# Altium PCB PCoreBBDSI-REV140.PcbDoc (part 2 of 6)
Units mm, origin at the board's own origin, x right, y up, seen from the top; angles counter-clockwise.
Board outline 100 x 72 mm, 6 copper layers (Top Layer, Int1 (GND), Int2 (Sign), Int3 (Sign), Int4 (GND), Bottom Layer), stack 1.551 mm thick; 358 components, 403 nets, 1535 pads, 844 vias.
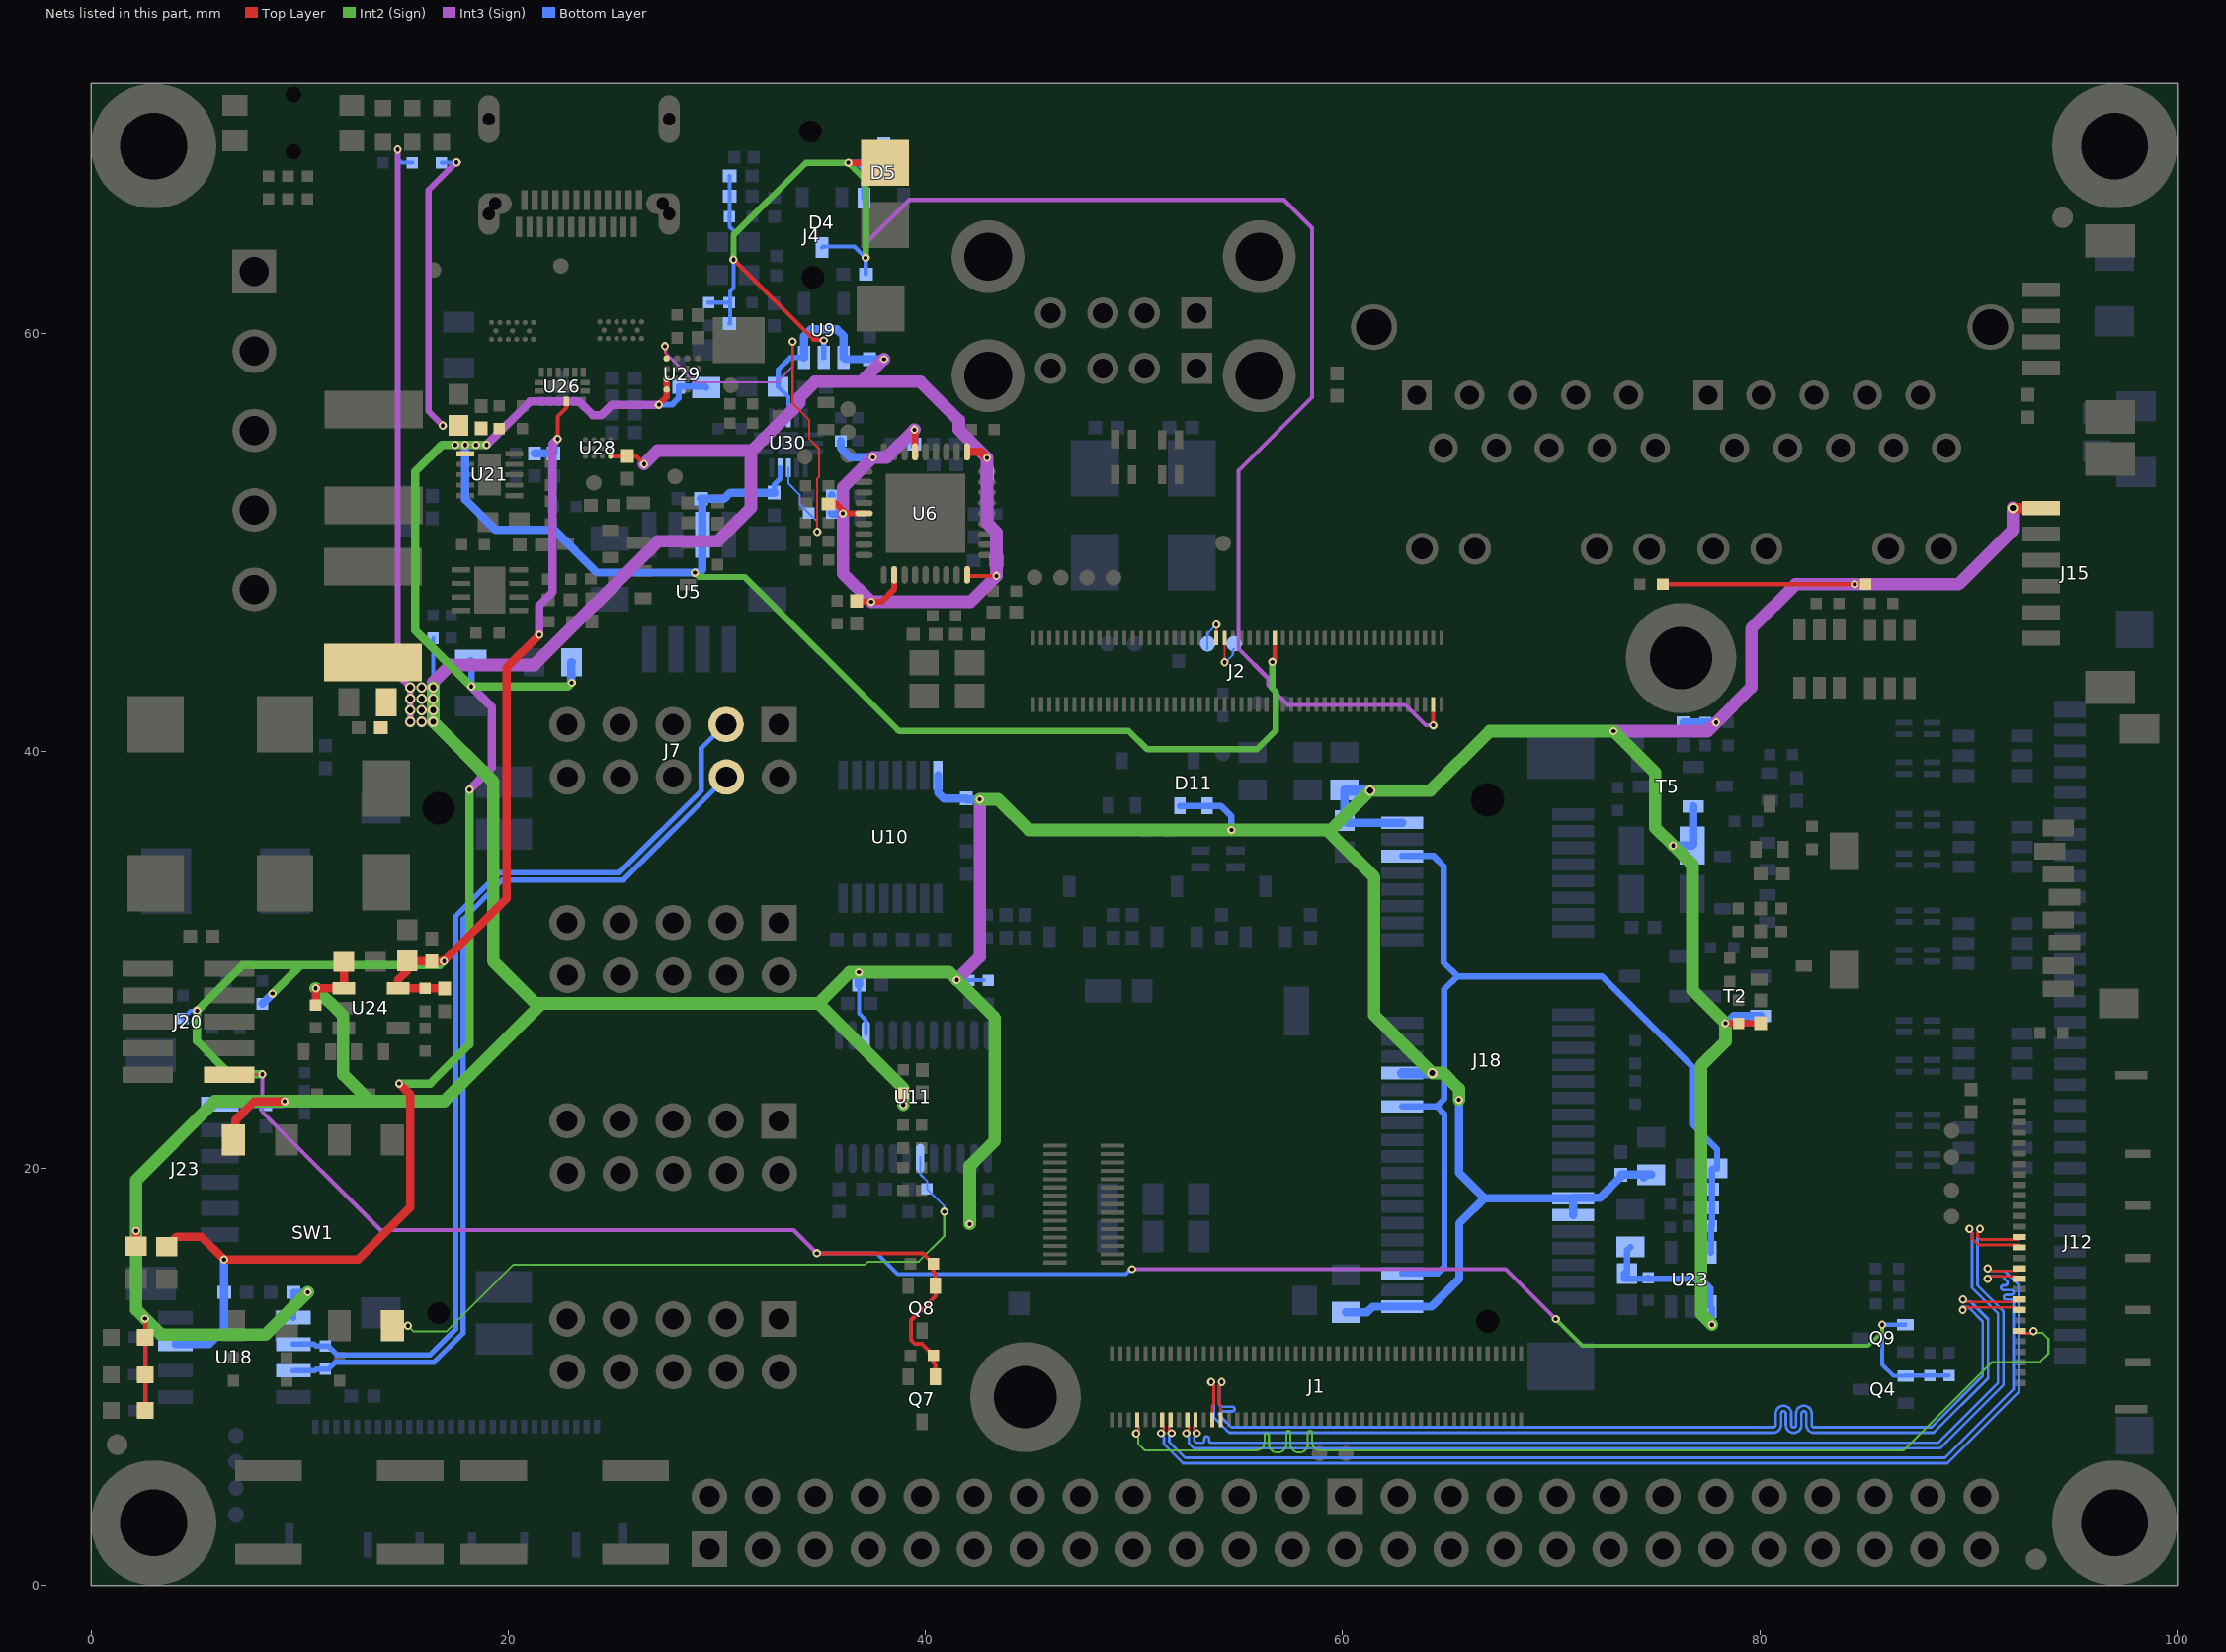
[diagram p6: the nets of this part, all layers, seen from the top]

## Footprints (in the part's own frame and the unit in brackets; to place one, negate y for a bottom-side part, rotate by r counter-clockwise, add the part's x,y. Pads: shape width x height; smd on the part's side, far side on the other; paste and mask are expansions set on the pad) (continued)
"F&S LOGO 5x5mm" [mm]
  Top Layer region: 0.175,2.098 0.382,2.013 0.578,1.917 0.765,1.813 0.941,1.699 1.105,1.577 1.257,1.448 1.396,1.31 1.522,1.166 1.633,1.015 1.73,0.858 1.811,0.696 1.875,0.528 1.923,0.356 1.953,0.18 1.966,0 0.226,0 0.138,0.011 0.072,0.041 0.026,0.083 -0.006,0.132 -0.025,0.18 -0.035,0.223 -0.04,0.265 -0.04,2.173
  Top Layer pour cut-out: 0.678,2.643 0.717,2.631 0.759,2.627 0.801,2.631 0.84,2.642 0.874,2.661 0.904,2.687 0.928,2.722 0.946,2.764 0.956,2.814 0.96,2.872 0.96,3.525 1.622,3.525 1.702,3.535 1.759,3.566 1.794,3.613 1.805,3.675 1.794,3.737 1.76,3.785 1.703,3.816 1.622,3.827 0.96,3.827 0.96,4.334 1.752,4.334 1.836,4.344 1.869,4.358 1.895,4.376 1.93,4.426 1.942,4.489 1.93,4.552 1.895,4.601 1.869,4.619 1.836,4.633 1.752,4.643 0.804,4.643 0.726,4.637 0.664,4.618 0.616,4.586 0.583,4.539 0.564,4.476 0.558,4.397 0.558,2.872 0.561,2.814 0.572,2.765 0.589,2.723 0.614,2.688 0.644,2.662
  Top Layer pour cut-out: 3.064,0.656 3.027,0.722 3,0.787 2.985,0.851 2.979,0.915 2.992,0.982 3.03,1.04 3.088,1.079 3.159,1.092 3.218,1.082 3.267,1.051 3.308,1.001 3.342,0.931 3.382,0.844 3.424,0.773 3.477,0.715 3.548,0.668 3.641,0.637 3.758,0.627 3.843,0.632 3.92,0.647 3.989,0.673 4.049,0.71 4.098,0.754 4.133,0.803 4.154,0.858 4.161,0.917 4.157,0.964 4.146,1.007 4.127,1.044 4.1,1.078 4.031,1.132 3.945,1.171 3.689,1.24 3.493,1.295 3.331,1.357 3.262,1.394 3.201,1.436 3.148,1.485 3.102,1.54 3.065,1.601 3.038,1.67 3.022,1.745 3.017,1.827 3.023,1.907 3.04,1.982 3.067,2.052 3.107,2.118 3.156,2.178 3.216,2.23 3.286,2.276 3.365,2.313 3.454,2.343 3.55,2.365 3.653,2.377 3.764,2.382 3.934,2.37 4.08,2.336 4.202,2.284 4.301,2.216 4.378,2.139 4.43,2.058 4.461,1.977 4.471,1.898 4.458,1.829 4.42,1.768 4.393,1.743 4.363,1.725 4.33,1.715 4.293,1.711 4.233,1.72 4.188,1.745 4.151,1.791 4.11,1.858 4.051,1.958 3.98,2.033 3.937,2.061 3.881,2.081 3.815,2.092 3.737,2.096 3.662,2.092 3.596,2.079 3.537,2.058 3.485,2.028 3.443,1.992 3.414,1.953 3.396,1.91 3.39,1.864 3.398,1.808 3.422,1.761 3.461,1.721 3.512,1.687 3.627,1.638 3.819,1.587 3.979,1.545 4.123,1.5 4.249,1.448 4.355,1.385 4.44,1.309 4.504,1.214 4.527,1.159 4.544,1.099 4.558,0.961 4.552,0.873 4.534,0.79 4.505,0.711 4.465,0.637 4.413,0.57 4.35,0.51 4.277,0.457 4.193,0.413 4.1,0.377 3.998,0.352 3.888,0.337 3.769,0.332 3.628,0.339 3.501,0.359 3.386,0.394 3.284,0.443 3.219,0.486 3.161,0.536 3.109,0.592
  Top Layer region: 2.907,3.777 2.992,3.656 3.084,3.538 3.185,3.423 3.293,3.312 3.408,3.204 3.532,3.1 3.662,2.999 3.807,2.899 3.957,2.806 4.112,2.718 4.273,2.637 4.438,2.563 4.608,2.495 4.782,2.433 4.96,2.378 4.96,0.265 4.949,0.178 4.919,0.112 4.877,0.065 4.828,0.034 4.78,0.015 4.737,0.005 4.694,0 2.401,0 2.831,3.901 hole: 3.764,2.382 3.653,2.377 3.55,2.365 3.454,2.343 3.365,2.313 3.286,2.276 3.216,2.23 3.156,2.178 3.107,2.118 3.067,2.052 3.04,1.982 3.023,1.907 3.017,1.827 3.022,1.745 3.038,1.67 3.065,1.601 3.102,1.54 3.148,1.485 3.201,1.436 3.262,1.394 3.331,1.357 3.493,1.295 3.689,1.24 3.945,1.171 4.031,1.132 4.1,1.078 4.127,1.044 4.146,1.007 4.157,0.964 4.161,0.917 4.154,0.858 4.133,0.803 4.098,0.754 4.049,0.71 3.989,0.673 3.92,0.647 3.843,0.632 3.758,0.627 3.641,0.637 3.548,0.668 3.477,0.715 3.424,0.773 3.382,0.844 3.342,0.931 3.308,1.001 3.267,1.051 3.218,1.082 3.159,1.092 3.088,1.079 3.03,1.04 2.992,0.982 2.979,0.915 2.985,0.851 3,0.787 3.027,0.722 3.064,0.656 3.109,0.592 3.161,0.536 3.219,0.486 3.284,0.443 3.386,0.394 3.501,0.359 3.628,0.339 3.769,0.332 3.888,0.337 3.998,0.352 4.1,0.377 4.193,0.413 4.277,0.457 4.35,0.51 4.413,0.57 4.465,0.637 4.505,0.711 4.534,0.79 4.552,0.873 4.558,0.961 4.544,1.099 4.527,1.159 4.504,1.214 4.44,1.309 4.355,1.385 4.249,1.448 4.123,1.5 3.979,1.545 3.819,1.587 3.627,1.638 3.512,1.687 3.461,1.721 3.422,1.761 3.398,1.808 3.39,1.864 3.396,1.91 3.414,1.953 3.443,1.992 3.485,2.028 3.537,2.058 3.596,2.079 3.662,2.092 3.737,2.096 3.815,2.092 3.881,2.081 3.937,2.061 3.98,2.033 4.051,1.958 4.11,1.858 4.151,1.791 4.188,1.745 4.233,1.72 4.293,1.711 4.33,1.715 4.363,1.725 4.393,1.743 4.42,1.768 4.458,1.829 4.471,1.898 4.461,1.977 4.43,2.058 4.378,2.139 4.301,2.216 4.202,2.284 4.08,2.336 3.934,2.37
  Top Layer region: 4.782,4.989 4.848,4.959 4.894,4.917 4.926,4.868 4.945,4.82 4.955,4.778 4.96,4.735 4.96,2.827 4.745,2.902 4.538,2.987 4.342,3.083 4.155,3.187 3.979,3.301 3.815,3.423 3.663,3.552 3.524,3.69 3.398,3.834 3.287,3.985 3.19,4.142 3.109,4.304 3.045,4.472 2.997,4.644 2.966,4.82 2.954,5 4.694,5
  Top Layer region: 2.089,1.099 2.012,1.223 1.928,1.344 1.836,1.462 1.735,1.577 1.627,1.688 1.512,1.796 1.388,1.9 1.257,2.001 1.113,2.101 0.963,2.194 0.808,2.282 0.647,2.363 0.482,2.437 0.312,2.505 0.138,2.567 -0.04,2.621 -0.04,4.735 -0.029,4.822 0.001,4.888 0.043,4.935 0.092,4.966 0.14,4.985 0.183,4.995 0.226,5 2.519,5 hole: 1.752,4.643 0.804,4.643 0.726,4.637 0.664,4.618 0.616,4.586 0.583,4.539 0.564,4.476 0.558,4.397 0.558,2.872 0.561,2.814 0.572,2.765 0.589,2.723 0.614,2.688 0.644,2.662 0.678,2.643 0.717,2.631 0.759,2.627 0.801,2.631 0.84,2.642 0.874,2.661 0.904,2.687 0.928,2.722 0.946,2.764 0.956,2.814 0.96,2.872 0.96,3.525 1.622,3.525 1.702,3.535 1.759,3.566 1.794,3.613 1.805,3.675 1.794,3.737 1.76,3.785 1.703,3.816 1.622,3.827 0.96,3.827 0.96,4.334 1.752,4.334 1.836,4.344 1.869,4.358 1.895,4.376 1.93,4.426 1.942,4.489 1.93,4.552 1.895,4.601 1.869,4.619 1.836,4.633
FH41-28S-0.5SH(05) [mm]
  rect 0.3x0.65 smd mask+0: 1(-6.75,2.975) 2(-6.25,2.975) 3(-5.75,2.975) 4(-5.25,2.975) 5(-4.75,2.975) 6(-4.25,2.975) 7(-3.75,2.975) 8(-3.25,2.975) 9(-2.75,2.975) 10(-2.25,2.975) 11(-1.75,2.975) 12(-1.25,2.975) 13(-0.75,2.975) 14(-0.25,2.975) 15(0.25,2.975) 16(0.75,2.975) 17(1.25,2.975) 18(1.75,2.975) 19(2.25,2.975) 20(2.75,2.975) 21(3.25,2.975) 22(3.75,2.975) 23(4.25,2.975) 24(4.75,2.975) 25(5.25,2.975) 26(5.75,2.975) 27(6.25,2.975) 28(6.75,2.975)
  rect 0.4x1.2 smd mask+0: 29(-5.75,-2.7) 30(-3.25,-2.7) 31(-0.75,-2.7) 32(1.75,-2.7) 33(4.25,-2.7)
  rect 0.4x1.55 smd mask+0: 40(-8,-2.4) 41(8,-2.4)
  body extent -9,-3.12 9,3.13, height 2.5
FIDUCIAL [mm] "Fiducial IPC2221A"
  round 1 smd paste+0 mask+0.5: 1(0,0)
  Top Layer keep-out circle w0.1: c0,0 r0.9
FUSE0805 [mm]
  rect 1x1.5 smd paste+0: 1(-1.1,0) 2(1.1,0)
  body extent -1.07,-0.67 1.07,0.67, height 1
HOLE-3.2x6 [mm]
  round 6 hole 3.2 paste+0 mask+0: 1(0,0)
HUQFN16 [mm]
  rect 0.25x0.45 smd paste-0.025 mask+0: 1(-1,-0.7) 2(-0.6,-0.7) 3(-0.2,-0.7) 4(0.2,-0.7) 5(0.6,-0.7) 6(1,-0.7) 9(1,0.7) 10(0.6,0.7) 11(0.2,0.7) 12(-0.2,0.7) 13(-0.6,0.7) 14(-1,0.7)
  rect 0.45x0.25 smd mask+0: 7(1.1,-0.2) 8(1.1,0.2) 15(-1.1,0.2) 16(-1.1,-0.2)
  rect 1.4x0.6 smd paste-10 mask+0: 17(0,0)
  body extent -1.23,-0.82 1.22,0.83, height 0.55
HX2QFN16 [mm] "QFN, 16-Leads, Body 2,60x2,60mm, Pitch 0,40mm, Thermal Pad 1,10x1,00mm, IPC Medium Density"
  rect 0.24x0.9 smd: 1(-0.8,-1.2) 2(-0.4,-1.2) 3(0,-1.2) 4(0.4,-1.2) 5(0.8,-1.2) 9(0.8,1.2) 10(0.4,1.2) 11(0,1.2) 12(-0.4,1.2) 13(-0.8,1.2)
  rect 0.9x0.24 smd: 6(1.2,-0.4) 7(1.2,0) 8(1.2,0.4) 14(-1.2,0.4) 15(-1.2,0) 16(-1.2,-0.4)
  rect 1x1.1 smd paste-0.25: 17(0,0)
  silkscreen extent -1.5,-2.27 1.5,1.5, body extent -1.35,-1.35 1.35,1.35, height 0.4
J-B2B-5X2-127MM-WR-PHD [mm]
  rect 0.76x2.4 smd paste+0: 1(-2.54,-1.95) 2(-2.54,1.95) 3(-1.27,-1.95) 4(-1.27,1.95) 5(0,-1.95) 6(0,1.95) 7(1.27,-1.95) 8(1.27,1.95) 9(2.54,-1.95) 10(2.54,1.95)
  body extent -3.17,-2.75 3.18,2.75, height 4.5
JAE-30POL. [mm]
  rect 0.6x1.5 smd paste+0.05: 1(14.5,-2.05) 2(13.5,-2.05) 3(12.5,-2.05) 4(11.5,-2.05) 5(10.5,-2.05) 6(9.5,-2.05) 7(8.5,-2.05) 8(7.5,-2.05) 9(6.5,-2.05) 10(5.5,-2.05) 11(4.5,-2.05) 12(3.5,-2.05) 13(2.5,-2.05) 14(1.5,-2.05) 15(0.5,-2.05) 16(-0.5,-2.05) 17(-1.5,-2.05) 18(-2.5,-2.05) 19(-3.5,-2.05) 20(-4.5,-2.05) 21(-5.5,-2.05) 22(-6.5,-2.05) 23(-7.5,-2.05) 24(-8.5,-2.05) 25(-9.5,-2.05) 26(-10.5,-2.05) 27(-11.5,-2.05) 28(-12.5,-2.05) 29(-13.5,-2.05) 30(-14.5,-2.05)
  rect 0.8x1.5 smd paste+0.05: 31(-15.5,-2.05) 32(15.5,-2.05)
  rect 1.8x1.8 smd paste+0.1: 33(-19.325,1.05) 34(19.325,1.05)
  body extent -20.03,-2.28 20.02,2.47, height 2.39
L0402 [mm] "Chip Inductor, 2-Leads, Body 1,00x0,50mm, IPC Medium Density"
  rect 0.59x0.62 smd: 1(-0.455,0) 2(0.455,0)
  body extent -0.53,-0.28 0.53,0.28, height 0.55
L0603 [mm] "Chip Inductor, 2-Leads, Body 1,60x0,80mm, IPC Medium Density"
  rect 0.93x1.02 smd: 1(-0.785,0) 2(0.785,0)
  body extent -0.9,-0.5 0.9,0.5, height 1
L1206 [mm] "Chip Inductor, 2-Leads, Body 3,20x1,60mm, IPC Medium Density"
  rect 1.19x1.82 smd: 1(-1.455,0) 2(1.455,0)
  silkscreen extent -0.5,-0.81 0.5,0.81, body extent -1.7,-0.9 1.7,0.9, height 1.3
LD-5X5M-VLC5045 [mm] "Precision Wire Wound Inductor, 2-Leads, Body 5,00x5,00mm, IPC Medium Density"
  rect 1.8x4.7 smd paste-0.1: 1(-2.3,0) 2(2.3,0)
  silkscreen extent -2.6,-2.6 2.6,2.6, body extent -2.49,-2.47 2.51,2.53, height 3.98
LED0603 [mm]
  rect 0.8x0.8 smd paste+0: 1(-0.825,0) 2(0.825,0)
  body extent -0.81,-0.4 0.8,0.4, height 0.75
LUMBERG-2410-03 [mm]
  round 3.5 hole 2.3 unplated paste+0 mask+0: 9(6.5,-2.85) 10(6.5,2.85) 11(-6.5,2.85) 12(-6.5,-2.85)
  rect 1.5x1.5 hole 0.95 unplated paste+0 mask+0: A1(3.5,0.15) B1(3.5,-2.5)
  round 1.5 hole 0.95 unplated paste+0 mask+0: A2(1,0.15) A3(-1,0.15) A4(-3.5,0.15) B2(1,-2.5) B3(-1,-2.5) B4(-3.5,-2.5)
  body extent -7.5,-4.1 7.5,13.92, height 16.21
MCDM(R)-04-T [mm]
  rect 1.1x1.5 smd: 1(-3.81,-4.45) 2(-1.27,-4.45) 3(1.27,-4.45) 4(3.81,-4.45) 5(3.81,4.45) 6(1.27,4.45) 7(-1.27,4.45) 8(-3.81,4.45)
  body extent -5.55,-4.9 5.55,4.9, height 4.36
MIC2026 [mm]
  rect 2.2x0.7 smd paste+0 mask+0: 1(-2.75,1.905) 2(-2.75,0.635) 3(-2.75,-0.635) 4(-2.75,-1.905) 5(2.75,-1.905) 6(2.75,-0.635) 7(2.75,0.635) 8(2.75,1.905)
  silkscreen extent -4.54,-2.49 1.25,2.49, body extent -3.01,-2.45 3.01,2.45, height 1.63
MICROSD_PUSH-PULL [mm]
  rect 0.8x1.5 smd paste+0.05: 1(-1.85,3.05) 2(-0.75,2.65) 3(0.35,3.05) 4(1.45,3.35) 5(2.55,3.05) 6(3.65,3.35) 7(4.75,3.05) 8(5.85,3.05)
  rect 1.4x1.9 smd paste+0.05: 9(-6.6,6.95) 12(6.55,5.95)
  rect 1.8x1.4 smd paste+0.05: 10(4.95,-7.2) 11(-0.75,-7.2)
  body extent -6.94,-7.6 7.06,7.6, height 1.83
MM60-52B1-E1-R650 [mm]
  rect 0.6x2 smd mask+0: 1(-11.8,-4.1) 2(-11.4,4.1) 3(-11,-4.1) 4(-10.6,4.1) 5(-10.2,-4.1) 6(-9.8,4.1) 7(-9.4,-4.1) 8(-9,4.1) 9(-8.6,-4.1) 10(-8.2,4.1) 11(-7.8,-4.1) 12(-7.4,4.1) 13(-7,-4.1) 14(-6.6,4.1) 15(-6.2,-4.1) 16(-5.8,4.1) 17(-2.2,-4.1) 18(-1.8,4.1) 19(-1.4,-4.1) 20(-1,4.1) 21(-0.6,-4.1) 22(-0.2,4.1) 23(0.2,-4.1) 24(0.6,4.1) 25(1,-4.1) 26(1.4,4.1) 27(1.8,-4.1) 28(2.2,4.1) 29(2.6,-4.1) 30(3,4.1) 31(3.4,-4.1) 32(3.8,4.1) 33(4.2,-4.1) 34(4.6,4.1) 35(5,-4.1) 36(5.4,4.1) 37(5.8,-4.1) 38(6.2,4.1) 39(6.6,-4.1) 40(7,4.1) 41(7.4,-4.1) 42(7.8,4.1) 43(8.2,-4.1) 44(8.6,4.1) 45(9,-4.1) 46(9.4,4.1) 47(9.8,-4.1) 48(10.2,4.1) 49(10.6,-4.1) 50(11,4.1) 51(11.4,-4.1) 52(11.8,4.1)
  rect 2.3x3.2 smd: 53(-14.65,-3.5) 54(14.65,-3.5)
  round 0 hole 1.6 unplated: 55(-12.5,0)
  round 0 hole 1.1 unplated: 56(12.5,0)
  body extent -14.85,-5 14.85,5, height 5.8
MM60-EZH059-B5-R650 [mm] "MINI EXPRESS CARD LATCH SMD"
  rect 1.5x2.7 smd paste+0.1 mask+0: ""(-13.35,-3.15) ""(-10.85,-3.15) ""(10.85,-3.15) ""(13.35,-3.15)
  round 0 hole 1.55 unplated: ""(-12.1,0)
  rect 1.5x1.9 smd paste+0.1 mask+0: ""(-12.1,2.75) ""(12.1,2.75)
  round 0 hole 1.05 unplated: ""(12.1,0)
  body extent -14.5,-3.95 14.5,3.95, height 6.8
R0402 [mm] "Chip Resistor, 2-Leads, Body 3,20x2,50mm, IPC Medium Density"
  rect 0.55x0.55 smd: 1(-0.55,0) 2(0.55,0)
  body extent -0.53,-0.28 0.52,0.28, height 0.4
R0805 [mm] "Chip Resistor, 2-Leads, Body 2,00x1,25mm, IPC Medium Density"
  rect 1x1.35 smd: 1(-0.9,0) 2(0.9,0)
  silkscreen extent -0.1,-0.58 0.1,0.58, body extent -1.05,-0.67 1.05,0.67, height 0.6
SF56K006VBAR2000 [mm] "Micro SIM Socket"
  rect 1x1.5 smd mask+0: C1(2.66,-4.34) C2(0.47,-4.34) C3(-1.72,-4.34) C5(2.66,-2.54) C6(0.47,-2.54) C7(-1.72,-2.54)
  rect 1x1.1 smd mask+0: DSW2(1,7.45) HD4(6.9,-7.55)
  rect 1.2x1.4 smd mask+0: HD1(-6.8,-7.4)
  rect 1.2x2.35 smd mask+0: HD2DSW1(-6.4,6.475)
  rect 1.75x1.1 smd mask+0: HD3(2.87,7.45)
  body extent -7.35,-8.1 7.35,8.1, height 1.27
SJ2-3574A-SMT-TR [mm]
  rect 2.2x2.5 smd: 1(5.4,-3.45)
  rect 2.2x2.3 smd: 2(3.9,3.35) 3(-0.1,3.55) 4(-3.1,3.55)
  round 1.1 hole 1.1 unplated: None(-4.6,0) None(2.4,0.1)
  body extent -8.1,-4.2 6.9,4.2, height 5.3
SOIC-8_M [mm] "SOIC, 8-Leads, Body 5x4mm, Pitch 1.27mm, IPC Low Density"
  rect 1.65x0.65 smd: 1(-2.825,1.905) 2(-2.825,0.635) 3(-2.825,-0.635) 4(-2.825,-1.905) 5(2.825,-1.905) 6(2.825,-0.635) 7(2.825,0.635) 8(2.825,1.905)
  silkscreen extent -2.95,-2.5 1.6,2.9, body extent -3,-2.5 3,2.5, height 1.75
SON50P250X80_HS-11N [mm] "SON, 10-Leads, Body 2,50x2,50mm, Pitch 0,50mm, Thermal Pad 2,00x1,09mm, IPC Medium Density"
  rect 0.85x0.25 smd: 1(-1.17,1) 2(-1.17,0.5) 3(-1.17,0) 4(-1.17,-0.5) 5(-1.17,-1) 6(1.17,-1) 7(1.17,-0.5) 8(1.17,0) 9(1.17,0.5) 10(1.17,1)
  rect 1.09x2 smd paste-0.2: 11(0,0)
  silkscreen extent -1.75,-1.45 1.3,1.5, body extent -1.3,-1.3 1.3,1.3, height 0.8
SOT23-3 [mm] "SOT23, 3-Leads, Body 2,92x2,37mm, Pitch 0,95mm, IPC Medium Density"
  rect 1x0.6 smd: 1(-1.2,0.95) 2(-1.2,-0.95) 3(1.2,0)
  silkscreen extent -1.33,-1.5 0.7,1.92, body extent -1.32,-1.52 1.32,1.52, height 1.12
SOT23-5 [mm] "SOT23, 5-Leads, Body 3,00x2,75mm, Pitch 0,95mm, IPC Medium Density"
  rect 1.1x0.6 smd: 1(-1.3,0.95) 2(-1.3,0) 3(-1.3,-0.95) 4(1.3,-0.95) 5(1.3,0.95)
  silkscreen extent -1.42,-1.5 0.35,1.93, body extent -1.5,-1.5 1.5,1.5, height 1.1
SOT23-6 [mm] "SOT23, 6-Leads, Body 2,95x2,95mm, Pitch 0,95mm, IPC Medium Density"
  rect 1.05x0.6 smd: 1(-1.4,0.95) 2(-1.4,0) 3(-1.4,-0.95) 4(1.4,-0.95) 5(1.4,0) 6(1.4,0.95)
  silkscreen extent -1.52,-1.55 0.5,1.92, body extent -1.55,-1.55 1.55,1.55, height 1.45
"SOT323 (SC70)" [mm]
  rect 0.8x0.55 smd: 1(-1.075,0.65) 2(-1.075,-0.65) 3(1.075,0)
  silkscreen extent -1.2,-1.1 0.67,1.6, body extent -1.15,-1.1 1.15,1.1, height 1.1
Spacer_M2 [mm]
  round 5.3 / inner round 0 / far side round 3.4 hole 3 paste+0: 1(0,0)
  body extent -2.17,-2.17 2.18,2.17, height 1.5
TESTPOINT [mm]
  round 0.75 smd paste-1: 1(0,0)
TRJG27440ADNL [mm] "2x RJ45 1000 Base-T integrated magnetics"
  rect 1.42x1.42 hole 0.9 unplated paste+0: L1(-1.27,4.4) R1(12.7,4.4)
  round 1.42 hole 0.9 unplated paste+0: L2(-2.54,6.94) L3(-3.81,4.4) L4(-5.08,6.94) L5(-6.35,4.4) L6(-7.62,6.94) L7(-8.89,4.4) L8(-10.16,6.94) L9(-11.43,4.4) L10(-12.7,6.94) R2(11.43,6.94) R3(10.16,4.4) R4(8.89,6.94) R5(7.62,4.4) R6(6.35,6.94) R7(5.08,4.4) R8(3.81,6.94) R9(2.54,4.4) R10(1.27,6.94)
  round 1.54 hole 1.02 unplated paste+0: L11(-1.525,11.77) L12(-4.065,11.77) L13(-9.905,11.77) R11(12.445,11.77) R12(9.905,11.77) R13(4.065,11.77) R14(1.55,11.79)
  round 1.542 hole 1.02 unplated paste+0: L14(-12.445,11.77)
  round 2.22 hole 1.7 unplated paste+0: L15(-14.8,1.14) R15(14.75,1.14)
  body extent -16.43,-12.7 16.4,12.7, height 15.28
TSSOP16-065M [mm] "TSOP, 16-Leads, Body 5,00x4,40mm, Pitch 0,65mm, IPC Medium Density"
  rect 1.4x0.45 smd: 1(-2.95,2.275) 2(-2.95,1.625) 3(-2.95,0.975) 4(-2.95,0.325) 5(-2.95,-0.325) 6(-2.95,-0.975) 7(-2.95,-1.625) 8(-2.95,-2.275) 9(2.95,-2.275) 10(2.95,-1.625) 11(2.95,-0.975) 12(2.95,-0.325) 13(2.95,0.325) 14(2.95,0.975) 15(2.95,1.625) 16(2.95,2.275)
  silkscreen extent -3.07,-2.55 1.85,3.18, body extent -3.2,-2.55 3.2,2.55, height 1.2
TSSOP24_065P [mm] "TSOP, 24-Leads, Body 7,80x4,40mm, Pitch 0,65mm, IPC Medium Density"
  oval 1.4x0.4 smd: 1(-2.95,3.575) 2(-2.95,2.925) 3(-2.95,2.275) 4(-2.95,1.625) 5(-2.95,0.975) 6(-2.95,0.325) 7(-2.95,-0.325) 8(-2.95,-0.975) 9(-2.95,-1.625) 10(-2.95,-2.275) 11(-2.95,-2.925) 12(-2.95,-3.575) 13(2.95,-3.575) 14(2.95,-2.925) 15(2.95,-2.275) 16(2.95,-1.625) 17(2.95,-0.975) 18(2.95,-0.325) 19(2.95,0.325) 20(2.95,0.975) 21(2.95,1.625) 22(2.95,2.275) 23(2.95,2.925) 24(2.95,3.575)
  silkscreen extent -3.07,-3.95 1.85,4.45, body extent -3.2,-3.95 3.2,3.95, height 1.2
UC-3019-2GNB-RR [mm]
  rect 0.3x0.95 smd mask+0: A1(-2.63,3.825) A2(-2.13,3.825) A3(-1.63,3.825) A4(-1.13,3.825) A5(-0.63,3.825) A6(-0.13,3.825) A7(0.37,3.825) A8(0.87,3.825) A9(1.37,3.825) A10(1.87,3.825) A11(2.37,3.825) A12(2.87,3.825) B1(2.62,2.525) B2(2.12,2.525) B3(1.62,2.525) B4(1.12,2.525) B5(0.62,2.525) B6(0.12,2.525) B7(-0.38,2.525) B8(-0.88,2.525) B9(-1.38,2.525) B10(-1.88,2.525) B11(-2.38,2.525) B12(-2.88,2.525)
  oval 1x2 hole 0.6 slot 1.6 at 90 deg mask+0: SH1(-4.32,3.2) SH2(4.32,3.2)
  oval 1.6x1 hole 0.6 slot 1.2 at 0 deg mask+0: SH1(-4.02,2.7) SH2(4.02,2.7)
  oval 1x2.3 hole 0.6 slot 1.9 at 90 deg mask+0: SH3(-4.32,-1.35) SH4(4.32,-1.35)
  body extent -4.47,-4.05 4.47,4.05, height 3.26
USB2514 [mm]
  oval 0.85x0.3 smd paste+0 mask+0: 1(-2.95,2) 2(-2.95,1.5) 3(-2.95,1) 4(-2.95,0.5) 5(-2.95,0) 6(-2.95,-0.5) 7(-2.95,-1) 8(-2.95,-1.5) 9(-2.95,-2) 19(2.95,-2) 20(2.95,-1.5) 21(2.95,-1) 22(2.95,-0.5) 23(2.95,0) 24(2.95,0.5) 25(2.95,1) 26(2.95,1.5) 27(2.95,2)
  oval 0.3x0.85 smd paste+0 mask+0: 10(-2,-2.95) 11(-1.5,-2.95) 12(-1,-2.95) 13(-0.5,-2.95) 14(0,-2.95) 15(0.5,-2.95) 16(1,-2.95) 17(1.5,-2.95) 18(2,-2.95) 28(2,2.95) 29(1.5,2.95) 30(1,2.95) 31(0.5,2.95) 32(0,2.95) 33(-0.5,2.95) 34(-1,2.95) 35(-1.5,2.95) 36(-2,2.95)
  rect 3.8x3.8 smd paste-5 mask+0: 37(0,0)
  silkscreen extent -4.08,-3.05 3.05,3.05, body extent -3.03,-3 2.97,3, height 1.03
USBSHOCK4-0805-12 [mm] "Chip Common Mode Choke Coil"
  rect 0.9x0.4 smd paste+0 mask+0: 1(-0.85,0.4) 2(0.85,0.4) 3(0.85,-0.4) 4(-0.85,-0.4)
  body extent -1,-0.6 1,0.6, height 1.2
WDFN8_0.65P_300X80 [mm] "WDFN, 8-Leads, Body 3,00x3,00mm, Pitch 0,65mm, Thermal Pad 2,23x1,48mm, IPC Medium Density"
  rect 0.9x0.25 smd mask+0: 1(-1.39,0.975) 2(-1.39,0.325) 3(-1.39,-0.325) 4(-1.39,-0.975) 5(1.39,-0.975) 6(1.39,-0.325) 7(1.39,0.325) 8(1.39,0.975)
  rect 1.48x2.23 smd paste-10 mask+0: 9(0,0)
  silkscreen extent -2.12,-1.68 1.68,1.72, body extent -1.58,-1.53 1.58,1.53, height 0.8
WE-SL5 [mm] "SMD Inductor, Body 9.0 x 10.3 mm"
  rect 2.7x2.7 smd: 1(-3.81,-3.11) 2(3.81,-3.11) 3(3.81,3.11) 4(-3.81,3.11)
  silkscreen extent -5.08,-4.44 5.08,4.44, body extent -5,-4.35 5,4.35, height 5.6
WLCSP12 [mm] "BGA, 12-Leads, Body 1,27x1,67mmx0,56mm, Pitch 0,40mm"
  round 0.25 smd: A1(-0.6,-0.4) A2(-0.6,0) A3(-0.6,0.4) B1(-0.2,-0.4) B2(-0.2,0) B3(-0.2,0.4) C1(0.2,-0.4) C2(0.2,0) C3(0.2,0.4) D1(0.6,-0.4) D2(0.6,0) D3(0.6,0.4)
  silkscreen extent -0.99,-0.79 -0.89,-0.69, body extent -0.84,-0.63 0.83,0.64, height 0.55
WLCSP15 [mm] "BGA, 15-Leads, Body 2,37x1,17mmx0,60mm, Pitch 0,40mm"
  round 0.25 smd paste+0 mask+0.038: A1(-0.4,-1) A2(-0.4,-0.6) A3(-0.4,-0.2) A4(-0.4,0.2) A5(-0.4,0.6) A6(-0.4,1) B1(0,-0.8) B2(0,0) B3(0,0.8) C1(0.4,-1) C2(0.4,-0.6) C3(0.4,-0.2) C4(0.4,0.2) C5(0.4,0.6) C6(0.4,1)
  silkscreen extent -0.74,-1.34 -0.64,-1.24, body extent -0.59,-1.18 0.58,1.19, height 0.58
WLCSP16 [mm] "BGA, 16-Leads, Body 2,05x2,05mmx0,60mm, Pitch 0,50mm"
  round 0.31 smd: A1(-0.75,-0.75) A2(-0.75,-0.25) A3(-0.75,0.25) A4(-0.75,0.75) B1(-0.25,-0.75) B2(-0.25,-0.25) B3(-0.25,0.25) B4(-0.25,0.75) C1(0.25,-0.75) C2(0.25,-0.25) C3(0.25,0.25) C4(0.25,0.75) D1(0.75,-0.75) D2(0.75,-0.25) D3(0.75,0.25) D4(0.75,0.75)
  silkscreen extent -1.18,-1.18 -1.08,-1.08, body extent -1.02,-1.02 1.02,1.02, height 0.6
XTALD-4-302X205M [mm]
  rect 1.4x1.2 smd paste-0.12: 1(-1.1,-0.8) 2(1.1,-0.8) 3(1.1,0.8) 4(-1.1,0.8)
  body extent -1.61,-1.25 1.61,1.25, height 0.81

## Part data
C1 C2: library part 473, "1nF  10%  2kV  X7R  1206", Temperature=-55/+125°C, Tolerance=10, Voltage=2kV
C3 C6 C7 C8 C9 C10 C11 C12 C13 C14 C19 C21 C22 C25 C33 C34 C35 C36 C37 C38 C39 C40 C41 C42 C43 C44 C45 C46 C47 C49 C50 C53 C54 C60 C66 C69 C70 C71 C74 C76 C78 C80 C82 C86 C90 C93 C94 C95 C96 C97 C100 C101 C105 C106: library part 380, "100nF  10%  16V  X7R  0402", Temperature=-55/+125°C, Tolerance=10, Voltage=16V
C4 C5 C72: library part 718, "220uF  20%  10V  2312  Typ: C", Temperature=-55/+125°C, Tolerance=20, Voltage=10V
C15 C16 C23 C30 C31 C32 C98: library part 394, "10uF  20%  4V  X5R  0402", Temperature=-55/+85°C, Tolerance=20, Voltage=4V
C17 C18 C20: library part 384, "22pF  5%  25V  C0G/NP0  0402", Temperature=-55/+125°C, Tolerance=5, Voltage=25V
C24 C28: library part 374, "220pF  10%  50V  X7R  0402", Temperature=-55/+125°C, Tolerance=10, Voltage=50V
C26 C27 C104: library part 412, "22uF  20%  6,3V  X5R  0603", Temperature=-55/+85°C, Tolerance=0,2, Voltage=6,3V
C29: library part 393, "12pF  5%  50V  C0G/NP0  0402", Temperature=-55/+125°C, Tolerance=5, Voltage=50V
C55 C56 C57 C58 C59: library part 390, "47pF  10%  50V  C0G/NP0  0402", Temperature=-55/+125°C, Tolerance=10, Voltage=50V
C61 C62 C63 C64 C99: library part 442, "47uF  20%  6,3V  X5R  0805", Temperature=-55/+85°C, Tolerance=20, Voltage=6,3V
C65 C75 C77 C79 C87 C88 C91 C92: library part 406, "10uF  20%  6,3V  X5R  0603", Temperature=-55/+85°C, Tolerance=20, Voltage=6,3V
C81: library part 387, "100pF  5%  25V  C0G/NP0  0402", Temperature=-55/+125°C, Tolerance=5, Voltage=25V
C83: library part 439, "0,22uF  10%  6,3V  X7R  0805", Temperature=-55/+125°C, Tolerance=10, Voltage=6,3V
C84 C85 C89: library part 388, "560pF  5%  25V  X7R  0402", Temperature=-55/+125°C, Tolerance=5, Voltage=25V
C102: library part 381, "1nF  10%  25V  X7R  0402", Temperature=-55/+125°C, Tolerance=10, Voltage=25V
C103: library part 392, "2,2uF  20%  6,3V  X5R  0402", Temperature=-55/+85°C, Tolerance=20, Voltage=6,3V
D1 D3 D10 D11 D12: library part 2695, "BAT54CW  30V  200mA  Dual Common Cathode SOT-323", Power=200mA, Temperature=-55°C/+125°C, Voltage=30V
D2 D4 D5 D6 D7 D8: library part 2709, "2 Channel ESD Protection TVS Diode SOT-23-3", Number devices in Package=1, Part Number=PGB102ST23WR, Temperature=-65/+125°C
D9: library part 2696, "SK56L-TP  60V  5A  Common Anode  DO-214AB", Power=5A, Temperature=-55°C/+150°C, Voltage=60V
D13 D14 D15 LED1 LED2 LED3: library part 2744, "LED  Green  View 120°  0603", Part Number=APT1608CGCK
F1 F2: library part 2718, "FUSE PTC RESETTABLE SMD 0805", Temperature=-40/+85°C
J3: library part 2764, "30 pol. 2 reih. Steckerl. SMD RM0,4"
J4: library part 2711, "Audio-Buchse liegend HP+MIC"
J5: library part 2784, "USB Typ C Buchse liegend SMD"
J6: library part 2712, "SD-CARD Micro Steckverbinder push-pull", Part Number="693 071 010 811"
J7 J8 J9 J10: library part 2714, "Stiftl. mit Wanne 10 pol. 2 reih.  steh."
J11: library part 2717, "Stiftl. 50 pol. 2 reih. RM2,54 H=5,8mm"
J12 J22: library part 2781, Temperature=-40/+105°C
J13: library part 2728, "FPC 30 pol. 1.00mm side entry SMT"
J14: library part 2721, "Stiftl. 4 pol. crimpable  liegend RM:1.25"
J15 J23: library part 2720, "Stiftl. 6 pol. crimpable  liegend RM:1.25"
J17: library part 2727, "Micro SIM Steckverbinder push-push"
J18: library part 2713, "mini PCIe SMD 52 pin", Part Number=MM60-52B1-E1-R650
J19: library part 2729, "Stiftl. 5 pol.1 reih. R3,81  liegend"
J20: library part 2706, "Stiftl. 10 pol. 2 reih. SMD RM:1,27", Part Number=M50-3610542
J21: library part 2704, "USB-Einbaukupplung zweifach liegend Typ A", Part Number="2410 03"
L1 L2 L11 L16: library part 2705, "WE-CBF  25%  700R  90MHz  EMI  1206", Part Number=74279218, Temperature=-55/+125°C
L3 L4 L22: library part 2698, "Common Mode Choke  20%  2x 90 Ohm  0805", Power=400mA, Temperature=-40°C/+125°C, Tolerance=20%
L5 L6 L7: library part 2708, "WE-CBF  25%  120R  100MHz  EMI  0402", Part Number=74279271, Temperature=-55/+125°C
L8 L9: library part 2707, "Ferritperlen  25%  120R  100MHz  0603", Part Number=74279262, Temperature=-55/+125°C
L10 L12 L13 L14 L15 L17 L18 L19 L20 L21: library part 2731, "Common Mode Choke  20%  2x 90 Ohm  0504", Part Number=DLP11SN900HL2L, Power=150mA, Temperature=-40/+85°C, Tolerance=20%, Voltage=5V
L23: library part 2697, "2x470uH 1,6A SMD", Power=1,6A
L24 L25: library part 2741, Power=4A
M1: library part 2734, "MINI EXPRESS CARD LATCH SMD"
Q1 Q2 Q5 Q6 T1 T3 T4 T6: library part 2689, "BSS138W SOT323(SC-70) N-Kanal", Temperature=-55°C/150°C
Q3: library part 2757, "24MHz 12pF 3.2x2.5 SMD", Part Number=Q22FA2380038014, Temperature=-40/+85°C
Q4 Q7 Q8 Q9: library part 2772, "MOSFET N-CH 20V 1.4A SOT323(SC-70)", Power=0,5W, Temperature=-55°C/150°C, Voltage=20V
R1: library part 6, "0R00 0,125W max 5% SMD 0805", Power=0,125W, Tolerance=5
R2 R76: library part 187, "0,01R 1/4W max 5% SMD 0805", Power=1/4W, Tolerance=5
R3 R4 R6 R7 R14 R15 R16 R17 R18 R21 R30 R31 R34 R35 R36 R37 R38 R54 R55 R56 R60 R62 R68 R78 R83 R86 R92 R93 R94 R96 R98: library part 170, "10k 1/16W 1% SMD 0402", Power=1/16W, Tolerance=1
R5 R8 R9 R48 R50 R99 R100 R101: library part 184, "4k7 1/16W max 5% SMD 0402", Power=1/16W, Tolerance=5
R10 R11 R32 R33 R39 R40 R41 R42 R69 R70 R95 R97 R102: library part 173, "0R 1/16W max 5% SMD 0402", Power=1/16W, Tolerance=5
R12 R91: library part 180, "1M 1/16W 1% SMD 0402", Power=1/16W, Tolerance=1
R13: library part 183, "12k 1/16W 1% SMD 0402", Power=1/16W, Tolerance=1
R19 R49 R65 R66 R73: library part 177, "100k 1/16W 1% SMD 0402", Power=1/16W, Tolerance=1
R20 R23 R24 R28 R29: library part 170, "10k 1/16W 1% SMD 0402", Part Number=10k, Power=1/16W, Tolerance=1
R22 R43 R44 R45 R57 R58 R59 R79: library part 166, "1k 1/16W 1% SMD 0402", Power=1/16W, Tolerance=1
R25 R27: library part 242, "49R9 1/16W 1% SMD 0402", Power=1/16W, Tolerance=1
R26 R47 R71: library part 186, "47k 1/16W 1% SMD 0402", Power=1/16W, Tolerance=1
R46: library part 179, "22k 1/16W 1% SMD 0402", Power=1/16W, Tolerance=1
R51: library part 309, "120R 1/16W 1% SMD 0402", Power=1/16W, Tolerance=1
R52 R53: library part 190, "300R 1/16W 1% SMD 0402", Power=1/16W, Tolerance=1
R63: library part B.R000.2.S, "0R00 0,125W max 5% SMD 0805", Part Number=0R00, Power=0,125W, Tolerance=5
R64 R84 R87: library part 204, "150k 1/16W 1% SMD 0402", Power=1/16W, Tolerance=1
R67: library part 303, "16.5k 1/16W 1% SMD 0402", Power=1/16W, Tolerance=1
R72 R85: library part 191, "75k 1/16W 1% SMD 0402", Power=1/16W, Tolerance=1
R74: library part Resistor
R75: library part 197, "30k1 1/16W 1% SMD 0402", Power=1/16W, Tolerance=1
R77: library part 254, "24k 1/16W 1% SMD 0402", Power=1/16W, Tolerance=1
R80 R82: library part 172, "150R 1/16W 1% SMD 0402", Power=1/16W, Tolerance=1
R81: library part 174, "221R 1/16W 1% SMD 0402", Power=1/16W, Tolerance=1
R88: library part 326, "56k 1/16W 1% SMD 0402", Power=1/16W, Tolerance=1
R89: library part 337, "23K2 / 1/16W / 1% / SMD / 0402", Power=1/16W, Tolerance=1
R90: library part 273, "53k6 1/16W 1% SMD 0402", Power=1/16W, Tolerance=1
SP1 SP2: library part 2747, "SMD-Distanzbolzen 1.5mm M2", Part Number=9774015243R
SW1: "Kodierschalter 4 pol. SMD", Part Number=MCDM(R)-04-T
T2 T5: library part 2691, "Si2301BDS SOT-23 P-Kanal", Temperature=-55°C/150°C
T10 T11: library part 2735, "Miniatur-Tastschalter Serie EVQ SMD", Power="20 mA", Temperature=-40/+85°C, Voltage=15V
T12: library part 2736, "Tact Switch side push", Temperature=-40/+85°C, Voltage=12V
U5: library part 1285, "MIC2026-1 USB Power Switch", Temperature=-40°C/+85°C, Voltage=2.7...5.5V
U6: library part 1255, "USB2514B C-Temp.", Temperature=0°C/+70°C
U7 U8 U12 U13 U14 U15 U16: library part 2710, "4 Channel  5,5V  TVS Diode Array  SOT-23-6", Part Number=AOZ8904CIL, Temperature=-40/+125°C
U9: library part 1748, "LDO 3.3V 600mA SOT-25 SMD", Part Number=AP7365, Power=600mA, Temperature=-40°C/+85°C, Voltage=3.3V
U10: library part 1210, "SP3232ECY SMD TSSOP16  C-Temp.", Temperature=0°C/+70°C, Voltage=3...5,5V
U11: library part 2755, "SP330E / TSSOP24 / SMD / RS-232/RS-485 Transceiver", Part Number=SP330EEY-L/TR, Temperature=-40/+85°C, Voltage=3...5.5V
U18: library part 1269, Temperature=-40°C/+150°C, Voltage=3…5V
U20: library part 1726, "NCP303LSN30T1G  3V  TSOP-5", Temperature=-40/+125°C
U21: library part 2789, "RT6150B DFN10 2.5x2.5mm"
U22: library part 1736, "RT8070ZQW ADJ 4A Sync WDFN-8 (-40°C bis 85°C)", Power=4A, Temperature=-40/+85°C, Voltage="max. 5,5V"
U23 U24: library part 1740, "ADP171AUJZ-R7 ADJ 300mA VIN max. 3,6V TSOT-5 SMD", Power=300mA, Temperature=-40°C/+125°C, Voltage=3,6V
U25 U27: library part 2765, "USB3.0 EMI filter & ESD Protection", Temperature=-40/+125°C, Voltage=-0.5...5V
U26: library part 2766, "High-speed differential 1-to-2 switch", Part Number=CBTU02043HEJ, Temperature=-10/+85°C, Voltage=1.62...3.63V
U28: library part 2767, "USB Type-C CC and SBU Protection IC", Part Number=NX20P0407UK, Temperature=-40/+85°C, Voltage=-0.5...6V
U29: library part 1328, "USB PD and Type-C current-limited power switch"
U30: library part 2770, "USB PD TCPC PHY IC", Temperature=-40/+85°C, Voltage=2.7...5.5V

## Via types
v1: diameter 0.4, hole 0.2, Top Layer to Bottom Layer, tented both sides, 716 vias
v2: diameter 0.5, hole 0.3, Top Layer to Bottom Layer, tented both sides, 102 vias
v3: diameter 0.4, hole 0.2, Top Layer to Bottom Layer, tented bottom, 16 vias
v4: diameter 0.9, hole 0.9, Top Layer to Bottom Layer, 6 vias
v5: diameter 0.5, hole 0.5, Top Layer to Bottom Layer, 2 vias
v6: diameter 3.2, hole 3.2, Top Layer to Bottom Layer, tented both sides, 2 vias

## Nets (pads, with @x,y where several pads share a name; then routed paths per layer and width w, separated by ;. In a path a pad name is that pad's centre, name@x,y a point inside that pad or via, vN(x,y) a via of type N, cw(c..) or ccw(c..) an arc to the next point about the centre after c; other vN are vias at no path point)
+1V5: C85.2 C86.2 C87.2 J18.6 J18.28 J18.48 R84.2 U23.5 | length 48.5
  Bottom Layer w0.305: J18.48@62.85,14.96 64.56,14.96 64.88,15.28 64.88,22.59 64.51,22.96 ; J18.28@62.85,22.96 64.51,22.96 ; J18.6@62.85,34.96 64.36,34.96 64.85,34.47 64.85,29.85 65.5,29.2 ; U23.5@77.65,15.95 77.65,17.2 77.705,17.255 77.705,18.049 77.71,18.054 C86.2@77.71,19 77.71,19.96 C87.2@77.74,19.99 ; C87.2@77.95,19.99 77.95,20.91 76.75,22.11 76.75,24.87 72.42,29.2 65.5,29.2 ; 64.51,22.96 64.87,23.32 64.87,28.57 65.5,29.2
+1V8: C89.2 C90.2 C91.2 C97.2 C98.2 J20.1 Q4.1 Q7.1 Q8.1 Q9.1 R6.2 R7.2 R50.2 R87.2 R99.2 R100.2 R101.2 U24.5 U26.4 | length 164.3
  Top Layer w0.1: J20.1@6.62,24.48 6.64,24.5 v1(8.21,24.5)
  Top Layer w0.2: v1(22.37,54.96) 22.37,56.04 22.79,56.46 U26.4@22.79,56.76 ; v1(34.79,15.92) 39.88,15.92 R100.2@40.38,15.42 40.38,15.02 40.48,14.92 Q8.1@40.48,14.365 40.48,13.88 39.31,12.71 39.31,11.777 39.497,11.59 39.82,11.59 R99.2@40.38,11.03 40.38,10.69 40.48,10.59 Q7.1@40.48,9.995
  Top Layer w0.4: C89.2@16.95,28.61 16.94,28.62 R87.2@16.02,28.62 U24.5@14.72,28.62 14.72,29.03 15.16,29.47 C91.2@15.16,29.93 16.32,29.93 C90.2@16.33,29.92 16.91,29.92 v1(16.92,29.93) 19.92,32.93 19.92,44 v1(21.493,45.573)
  Int2 (Sign) w0.2: v1(70.21,12.77) 71.49,11.49 85.19,11.49 85.86,12.16 v1(85.86,12.5)
  Int2 (Sign) w0.4: v1(8.21,24.5) 6.68,24.5 5.08,26.1 v1(5.08,27.55) 7.26,29.73 10.06,29.73 ; v1(8.7,28.37) 10.06,29.73 ; 11,29.73 10.06,29.73 ; v1(16.92,29.93) 16.72,29.73 10.06,29.73
  Int3 (Sign) w0.2: v1(8.21,24.5) 8.21,22.7 13.88,17.03 33.68,17.03 v1(34.79,15.92) ; v1(49.896,15.16) 67.82,15.16 v1(70.21,12.77)
  Int3 (Sign) w0.4: v1(21.493,45.573) 21.493,46.983 22.12,47.61 22.12,54.71 v1(22.37,54.96)
  Bottom Layer w0.2: R7.2@4.4,27.18 4.77,27.55 v1(5.08,27.55) ; v1(34.79,15.92) 37.672,15.92 38.672,14.92 49.602,14.92 49.842,15.16 v1(49.896,15.16) ; Q9.1@86.975,12.5 v1(85.86,12.5) 85.86,10.58 86.4,10.04 Q4.1@86.985,10.04 87.005,10.06 R101.2@88.14,10.06 R50.2@89.06,10.06
  Bottom Layer w0.4: R6.2@8.21,27.88 v1(8.7,28.37) ; C98.2@21.26,54.26 C97.2@22.17,54.26 22.17,54.76 v1(22.37,54.96)
+3V3: C9.2 C10.2 C11.2 C12.2 C13.2 C21.2 C31.2 C34.1 C39.1 C44.2 C47.2 C49.2 C61.2 C62.2 C63.2 C64.2 C65.2 C66.2 C82.2 C83.2 C88.2 C92.2 C101.2 C104.2 D11.1 D11.2 J15.1 J18.2 J18.24 J18.39 J18.41 J18.52 J23.1 L8.1 L11.1 L25.2 LED1.2 LED2.2 LED3.2 R11.1 R26.2 R33.1 R34.1 R35.1 R37.1 R46.2 R52.1 R53.1 R72.2 R80.2 R83.1 R86.1 R92.2 R93.2 R98.2 SW1.8 T2.2 T5.2 U6.10 U6.15 U6.23 U6.29 U6.36 U9.1 U9.3 U10.16 U11.3 U18.5 U23.1 U24.1 U28.A3 U30.3 | length 431.4
  Top Layer w0.2: v1(2.59,12.79) 2.605,12.775 LED1.2@2.605,11.89 LED2.2@2.605,10.1 LED3.2@2.605,8.38 ; U28.A3@24.9,54.12 25.7,54.12 C101.2@25.71,54.13 26.13,54.13 v1(26.51,53.75) ; U6.36@42,48.39 v1(43.4,48.39) v1@43.5,48.39 ; R53.1@75.347,48.036 75.393,47.99 v1(84.55,47.99) R52.1@85.06,47.99
  Top Layer w0.3: C13.2@35.34,51.85 35.73,51.85 36.04,51.54 v1(36.04,51.39) U6.23@37,51.39 ; C10.2@36.7,47.15 v1(37.4,47.15) 37.9,47.15 38.5,47.75 U6.29@38.5,48.39 ; v1(38.94,23.04) R33.1@38.94,23.61 ; v1(39.47,55.4) v1@39.501,55.4 ; U6.15@39.5,54.39 v1@39.5,55.343
  Top Layer w0.305: v1(78.35,26.95) R26.2@78.99,26.95 80.03,26.95 C21.2@80.04,26.96
  Top Layer w0.4: v1(2.16,17) 2.165,16.995 L8.1@2.165,16.255 ; SW1.8@6.83,21.35 6.92,21.44 6.92,22.3 7.83,23.21 v1(9.28,23.21) ; R86.1@10.77,27.82 v1(10.77,28.62) U24.1@12.12,28.62 C92.2@12.12,29.89 ; U6.10@42.06,54.34 42.66,54.34 v1(42.95,54.05)
  Top Layer w0.5: v2(92.13,51.65) 92.135,51.645 J15.1@93.49,51.645
  Int2 (Sign) w0.6: v1(2.16,17) v1@2.165,17 ; v1(10.39,14.053) 8.367,12.03 3.35,12.03 v1(2.59,12.79) 2.165,13.215 v1@2.165,17 ; v1(10.77,28.62) 12.09,27.3 12.09,24.487 13.367,23.21 ; v2(16.4,43.05) v2(16.4,42.5) v2(16.4,41.95) v2(16.4,41.4) 19.28,38.52 19.28,29.92 21.3,27.9 21.62,27.9 ; v1(38.94,23.04) 38.94,23.83 34.87,27.9 ; v1(42.12,17.32) 42.12,20.11 43.32,21.31 43.32,27.21 v1(41.5,29.03) 41.14,29.39 v1(36.81,29.39) 36.36,29.39 34.87,27.9 ; v1(42.6,37.68) 43.484,37.68 44.955,36.21 v1(54.67,36.21) 59.25,36.21 ; v1(65.57,23.28) 65.57,23.81 64.82,24.56 v2(64.29,24.56) 61.51,27.34 61.51,33.95 59.34,36.12 v2(61.32,38.1) 64.2,38.1 67.05,40.95 v1(72.99,40.95) ; v1@72.996,40.95 74.975,38.971 74.975,36.335 v1(75.84,35.47) 76.765,34.545 76.765,28.535 v1(78.35,26.95) 78.35,26.08 77.18,24.91 77.18,13.02 v1(77.7,12.5) ; v1@2.165,17 2.165,19.435 5.94,23.21 v1(9.28,23.21) 13.367,23.21 ; 13.367,23.21 16.93,23.21 21.62,27.9 ; 21.62,27.9 34.1,27.9 34.87,27.9
  Int3 (Sign) w0.2: 31.63,54.11 31.7,54.18
  Int3 (Sign) w0.3: v1(14.7,68.83) 14.7,43.65 v2(15.3,43.05) v2(15.3,41.4)
  Int3 (Sign) w0.6: v2(16.4,41.4) v2(16.4,41.95) v2(16.4,42.5) v2(16.4,43.05) 16.4,43.294 17.226,44.12 21.24,44.12 27.17,50.05 30.02,50.05 31.63,51.66 31.63,54.11 ; v1(26.51,53.75) 26.51,53.758 27.152,54.4 31.67,54.4 33.97,56.7 33.97,56.959 34.708,57.697 36.94,57.697 36.94,57.7 ; v1(38.01,58.78) 36.94,57.71 36.94,57.7 ; v1(39.47,55.4) 38.14,54.07 v1(37.48,54.07) 36.04,52.63 v1(36.04,51.39) 36.04,48.51 v1(37.4,47.15) 42.16,47.15 v1(43.4,48.39) 43.4,50.48 42.95,50.93 v1(42.95,54.05) 41.6,55.4 41.6,55.85 39.75,57.7 36.94,57.7 ; v1(41.5,29.03) 42.6,30.13 v1(42.6,37.68) ; v1(72.99,40.95) 77.49,40.95 v1(77.9,41.36) 79.59,43.05 79.59,45.87 81.71,47.99 v1(84.55,47.99) 89.52,47.99 92.13,50.6 v2(92.13,51.65)
  Bottom Layer w0.2: v1(14.7,68.83) 14.7,68.38 14.88,68.2 R80.2@15.4,68.2 ; v2(16.4,43.05) R72.2@16.4,45.4 ; C104.2@32.94,57.46 33.43,56.97 U30.3@33.43,55.96 ; C39.1@36.81,28.79 36.82,28.78 36.82,27.42 37.155,27.085 U11.3@37.155,26.44 ; v1(41.5,29.03) 41.51,29.02 41.62,29.02 41.63,29.01 R34.1@42.09,29.01 R35.1@42.8,29.01
  Bottom Layer w0.25: C104.2@32.94,57.46 32.94,58.27 33.53,58.86 U9.3@34.175,58.86
  Bottom Layer w0.3: U18.5@9.695,12.835 9.7,12.84 C49.2@9.7,14.04 C49.2@9.705,14.045
  Bottom Layer w0.305: C49.2@9.705,14.045 9.713,14.053 v1(10.39,14.053) ; D11.2@52.2,37.365 D11.1@53.5,37.365 54.175,37.365 54.67,36.87 v1(54.67,36.21) ; C88.2@73.49,14.95 73.49,14.7 74.59,14.7 R83.1@74.64,14.75 74.69,14.7 77.17,14.7 77.63,14.24 U23.1@77.63,13.36 ; C88.2@73.63,14.95 73.63,16.06 C62.2@73.79,16.22 ; v1(77.7,12.5) U23.1@77.7,13.3
  Bottom Layer w0.4: J23.1@6.17,23.075 8.365,23.075 C47.2@8.37,23.08 9.15,23.08 v1(9.28,23.21) ; U9.3@34.175,58.86 34.175,59.875 34.51,60.21 35.76,60.21 36.075,59.895 U9.1@36.075,58.86 ; R98.2@35.5,52.25 R92.2@35.5,51.41 35.52,51.39 v1(36.04,51.39) ; R93.2@35.94,54.87 35.94,54.52 36.39,54.07 v1(37.48,54.07) ; U9.1@36.17,58.78 C31.2@37.32,58.78 v1(38.01,58.78) ; C39.1@36.81,28.79 v1(36.81,29.39) ; C12.2@39.47,54.673 C12.2@39.47,54.7 39.47,54.791 v1(39.47,55.4) ; U10.16@40.605,38.83 40.605,37.985 40.87,37.72 C34.1@41.95,37.72 41.99,37.68 v1(42.6,37.68) ; v1(42.12,17.32) R37.1@42.12,17.91 ; v1(42.95,54.05) C11.2@42.95,53.28 ; C11.2@42.96,53.25 42.95,53.26 C11.2@42.95,53.28 ; C11.2@42.96,53.29 C11.2@42.95,53.28 ; v1(43.4,48.39) C9.2@43.4,49.12 R11.1@43.4,50.03 ; C65.2@60.09,36.66 C64.2@60.09,38.14 C64.2@60.13,38.1 ; C65.2@60.09,36.69 60.22,36.56 J18.2@62.85,36.56 ; C63.2@60.16,13.09 61.17,13.09 61.44,13.36 J18.52@62.85,13.36 64.25,13.36 65.59,14.7 65.59,17.36 66.79,18.56 ; v1(65.57,23.28) 65.57,19.78 65.65,19.7 65.7,19.65 66.79,18.56 ; J18.41@71.05,17.76 J18.39@71.05,18.56 ; C61.2@74.432,19.552 74.432,19.592 74.53,19.69 C61.2@74.8,19.69 ; C61.2@74.432,19.69 C66.2@73.34,19.69 73.34,19.59 72.329,18.579 71.069,18.579 J18.39@71.05,18.56 ; v1(75.84,35.47) L11.1@76.7,35.47 ; C44.2@76.32,41.34 76.34,41.36 R46.2@77.27,41.36 ; L11.1@76.755,35.47 76.8,35.515 T5.2@76.8,37.34 ; R46.2@77.38,41.36 R46.2@77.27,41.36 ; v1(77.9,41.36) R46.2@77.27,41.36 ; v1(78.35,26.95) 78.4,26.95 78.75,27.3 T2.2@80.04,27.3 ; 66.79,18.56 J18.39@71.05,18.56
  Bottom Layer w0.5: C64.2@60.13,38.1 v2(61.32,38.1) ; J18.24@62.85,24.56 v2(64.29,24.56)
  other v2: 15.85,41.4 15.3,41.95 15.85,41.95 15.3,42.5 15.85,42.5 15.85,43.05
+5VS: C3.2 C50.1 C75.2 C76.2 C99.2 C100.2 C105.2 F1.1 J2.41 L9.2 R63.2 R64.2 R81.2 U5.7 U18.3 U21.1 U29.A1 U29.A2 U30.12 | length 160
  Top Layer w0.2: v1@56.622,44.262 v1(56.63,44.27) ; v1@56.738,44.262 56.73,44.27 v1(56.63,44.27) ; J2.41@56.74,45.41 56.74,44.38 v1(56.63,44.27)
  Top Layer w0.3: v1(27.22,56.6) 27.59,56.97 U29.A1@27.59,57.32 U29.A2@27.59,57.82
  Top Layer w0.4: L9.2@3.62,16.245 3.665,16.245 3.93,16.51 3.93,16.555 4.095,16.72 5.28,16.72 v1(6.38,15.62) 12.8,15.62 15.3,18.12 15.3,23.53 v1(14.77,24.06)
  Int2 (Sign) w0.3: v1(28.945,48.545) 29.15,48.34 31.343,48.34 38.683,41 38.71,41 38.75,40.96 49.74,40.96 50.62,40.08 55.885,40.08 56.788,40.983 56.788,41.012 56.79,41.014 56.79,41.386 56.788,41.388 56.788,42.832 56.63,42.99 v1(56.63,44.27)
  Int2 (Sign) w0.4: v1(14.77,24.06) 16.27,24.06 18.14,25.93 v1(18.14,38.14) ; v1(18.96,54.67) v1(18.45,54.67) v1(17.94,54.67) v1(17.46,54.67) 16.82,54.67 15.55,53.4 15.55,45.77 v1(18.23,43.09) 22.86,43.09 v1(23.04,43.27)
  Int3 (Sign) w0.3: v1(16.86,55.6) 16.18,56.28 16.18,66.89 v1@17.51,68.22
  Int3 (Sign) w0.4: v1(17.46,54.67) v1(17.94,54.67) v1(18.45,54.67) v1(18.96,54.67) 21.04,56.75 23.4,56.75 24.05,56.1 24.467,56.1 24.967,56.6 v1(27.22,56.6) ; v1@17.51,68.22 v1(17.52,68.22) ; v1(18.14,38.14) 19.2,39.2 19.2,42.12 v1(18.23,43.09)
  Bottom Layer w0.2: R81.2@16.8,68.2 17.5,68.2 v1(17.52,68.22)
  Bottom Layer w0.25: C105.2@32.75,52.38 32.75,52.77 33.03,53.05 U30.12@33.03,53.56
  Bottom Layer w0.3: v1(27.22,56.6) 27.85,56.6 28.17,56.92 C100.2@28.17,57.46 29.45,57.46 C99.2@29.49,57.42
  Bottom Layer w0.305: F1.1@18.2,44.36 18.23,44.33 v1(18.23,43.09)
  Bottom Layer w0.4: U18.3@4.045,11.565 5.655,11.565 6.38,12.29 C50.1@6.38,14.04 v1(6.38,15.62) ; v1(17.94,54.67) 17.94,52.05 19.39,50.6 22.2,50.6 24.25,48.55 28.94,48.55 v1(28.945,48.545) ; v1(23.04,43.27) 23.03,43.28 23.03,44.25 R63.2@23.04,44.26 ; v1@28.945,48.56 29.17,48.56 29.305,48.695 U5.7@29.305,50.36 29.293,50.373 29.293,52.027 C3.2@29.23,52.09 30.35,52.09 30.64,52.38 C105.2@32.75,52.38
\RE: R38.2 SW1.4 U11.18 | length 32.7
  Top Layer w0.127: SW1.4@14.45,12.45 v1(15.19,12.45)
  Int2 (Sign) w0.1: v1(15.19,12.45) 15.468,12.172 17.039,12.172 20.247,15.38 37.107,15.38 37.247,15.52 39.67,15.52 40.9,16.75 v1(40.9,17.91)
  Bottom Layer w0.1: U11.18@39.755,20.54 39.755,19.705 40.08,19.38 R38.2@40.08,19 40.9,18.18 v1(40.9,17.91)
\USB_LD_FLT: R92.1 U29.A4 U30.11 | length 22.4
  Top Layer w0.1: v1(27.51,59.4) 27.51,59.319 27.59,59.239 U29.A4@27.59,58.82 ; v1(33.63,59.62) 33.63,56.675 34.42,55.885 34.42,54.978 34.9,54.498 34.9,54.328 34.9,53.14 34.801,53.041 34.801,50.509 v1(34.81,50.5)
  Int3 (Sign) w0.1: v1(27.51,59.4) 27.51,59.11 28.95,57.67 32.87,57.67 33.63,58.43 v1(33.63,59.62)
  Bottom Layer w0.1: U30.11@33.43,53.56 33.43,52.82 33.97,52.28 33.97,51.84 R92.1@34.4,51.41 34.81,51 v1(34.81,50.5)
\USB_OTG_ID: J2.55 TP25.1 | length 2
  Top Layer w0.1: J2.55@53.94,45.41 v1(53.94,46.05)
  Bottom Layer w0.1: TP25.1@53.52,44.89 53.52,45.63 v1(53.94,46.05)
\USB_OTG_PWR: J2.53 TP24.1 | length 2.6
  Top Layer w0.1: v1@54.35,44.25 54.34,44.26 54.34,44.849 ; 54.34,44.849 J2.53@54.34,45.41 54.34,44.849
  Bottom Layer w0.1: v1@54.35,44.23 54.732,44.612 54.732,44.832 TP24.1@54.79,44.89
  other v1: 54.34,44.25
AUDIO_A_GND: C24.2 C28.1 C29.1 C30.1 D4.3 D5.2 D5.3 J2.4 J4.4 R30.2 R31.1 R32.2 U9.2 | length 94.6
  Top Layer w0.2: v1(30.8,63.55) 34.63,59.72 34.862,59.72 34.863,59.718 35.132,59.718 v1@35.17,59.68 ; v1(64.34,41.23) J2.4@64.34,42.45
  Top Layer w0.3: v1(36.3,68.2) 36.45,68.2 J4.4@38.05,68.2
  Int2 (Sign) w0.3: v1(30.8,63.55) 30.8,64.73 34.27,68.2 v1(36.3,68.2) 37.14,67.36 37.14,63.65 v1(37.13,63.64)
  Int3 (Sign) w0.2: v1@35.17,59.68 v1@35.208,59.718 ; v1(37.13,63.64) 37.13,64.322 39.228,66.42 57.18,66.42 58.53,65.07 58.53,56.956 55.01,53.436 55.01,44.9 56.438,43.472 56.438,43.15 57.378,42.21 63,42.21 63.98,41.23 v1(64.34,41.23)
  Bottom Layer w0.2: R32.2@29.6,61.49 R30.2@30.59,61.49 R30.2@30.64,61.49 ; R31.1@30.59,65.64 30.61,65.66 C24.2@30.61,66.58 ; C28.1@30.6,60.48 30.64,60.48 R30.2@30.64,61.49 ; R31.1@30.6,65.62 30.61,65.61 30.61,65.12 30.8,64.93 v1(30.8,63.55) 30.8,62.2 30.64,62.04 R30.2@30.64,61.49 ; C24.2@30.61,66.6 C24.2@30.61,66.58 ; C29.1@30.61,67.57 C24.2@30.61,66.58 ; D4.3@35.04,64.13 35.09,64.18 36.59,64.18 v1(37.13,63.64) ; C30.1@37.14,62.85 v1@37.14,63.63
  Bottom Layer w0.254: U9.2@35.125,58.86 v1(35.125,59.68)
  Bottom Layer w0.3: v1(36.3,68.2) 36.76,68.2 ; D5.2@37.05,66.51 37.05,67.91 36.76,68.2 ; D5.3@38,68.91 38,68.378 37.822,68.2 36.76,68.2
CAN1H: J7.4 R51.2 U18.7 | length 44.2
  Bottom Layer w0.254: U18.7@9.695,10.295 10.735,10.295 10.81,10.37 R51.2@11.23,10.37 11.38,10.37 11.71,10.7 16.44,10.7 17.84,12.1 17.84,31.94 19.716,33.816 25.526,33.816 J7.4@30.46,38.75
CAN1L: J7.3 R51.1 U18.6 | length 46.2
  Bottom Layer w0.254: U18.6@9.695,11.565 10.695,11.565 10.79,11.47 R51.1@11.23,11.47 11.38,11.47 11.796,11.054 16.254,11.054 17.486,12.286 17.486,32.087 19.569,34.17 25.329,34.17 29.251,38.092 29.251,40.131 J7.3@30.39,41.27
CSI_A_CLK_N: J1.76 J12.9 | length 52.4
  Top Layer w0.127: v1(53.7,9.75) 53.7,9.692 53.82,9.573 53.82,9.078 53.82,8.7 53.748,8.628 J1.76@53.748,8.229 ; v1(89.73,13.7) 89.788,13.7 89.907,13.58 92.14,13.58 92.26,13.7 J12.9@92.435,13.7
  Bottom Layer w0.127: v1(53.7,9.75) 53.7,9.692 53.82,9.573 53.82,8.065 54.564,7.32 80.631,7.32 ccw(c80.631,7.708) 81.019,7.708 81.019,8.237 cw(c81.132,8.237) 81.132,8.351 cw(c81.132,8.237) 81.246,8.237 81.246,7.688 ccw(c81.62,7.688) 81.62,7.314 ccw(c81.62,7.688) 81.994,7.688 81.994,8.237 cw(c82.107,8.237) 82.107,8.351 cw(c82.107,8.237) 82.221,8.237 82.221,7.708 ccw(c82.609,7.708) 82.609,7.32 88.33,7.32 90.941,9.931 90.941,12.758 90.088,13.611 89.794,13.611 89.72,13.685 89.73,13.695 v1(89.73,13.7)
CSI_A_CLK_P: J1.74 J12.8 | length 52.4
  Top Layer w0.127: J1.74@54.148,8.229 54.148,8.632 54.08,8.7 54.08,9.186 54.08,9.573 54.2,9.692 v1(54.2,9.75) ; v1(89.72,13.2) 89.778,13.2 89.897,13.32 92.14,13.32 92.26,13.2 J12.8@92.435,13.2
  Bottom Layer w0.127: v1(54.2,9.75) 54.2,9.692 54.08,9.573 54.08,9.24 54.08,8.698 ccw(c54.207,8.698) 54.207,8.571 54.705,8.571 cw(c54.705,8.457) 54.705,8.344 54.207,8.344 ccw(c54.207,8.217) 54.08,8.217 54.08,8.173 54.256,7.996 54.672,7.581 80.059,7.581 80.631,7.581 ccw(c80.631,7.708) 80.758,7.708 80.758,8.237 cw(c81.132,8.237) 81.132,8.611 cw(c81.132,8.237) 81.506,8.237 81.506,7.688 ccw(c81.62,7.688) 81.62,7.574 ccw(c81.62,7.688) 81.733,7.688 81.733,8.237 cw(c82.107,8.237) 82.107,8.611 cw(c82.107,8.237) 82.482,8.237 82.482,7.708 ccw(c82.609,7.708) 82.609,7.581 83.29,7.581 88.222,7.581 90.68,10.039 90.68,12.65 90.05,13.28 89.98,13.35 89.894,13.35 89.881,13.337 89.781,13.337 89.72,13.276 v1(89.72,13.2)
CSI_A_DATA0_N: J1.82 J12.15 | length 52.6
  Top Layer w0.127: v1(52.5,7.3) 52.5,7.307 52.62,7.426 52.62,7.62 52.548,7.692 J1.82@52.548,8.229 ; v1(90.55,17.09) 90.55,17.032 90.43,16.913 90.43,16.726 90.577,16.58 92.423,16.58 92.435,16.592 J12.15@92.435,16.7
  Bottom Layer w0.127: v1(52.5,7.3) 52.5,7.242 52.62,7.123 52.62,6.829 52.878,6.57 88.641,6.57 91.681,9.61 91.681,13.127 90.43,14.378 90.43,16.913 90.55,17.032 v1(90.55,17.09)
CSI_A_DATA0_P: J1.80 J12.14 | length 52.6
  Top Layer w0.127: J1.80@52.948,8.229 52.948,7.688 52.88,7.62 52.88,7.426 53.007,7.3 v1(53.01,7.3) ; v1(90.05,17.09) 90.05,17.032 90.17,16.913 90.17,16.619 90.469,16.32 92.429,16.32 92.435,16.314 J12.14@92.435,16.2
  Bottom Layer w0.127: v1(53.01,7.3) 53.01,7.252 52.88,7.123 52.88,6.936 52.986,6.831 53.035,6.831 53.24,6.831 ccw(c53.24,6.958) 53.367,6.958 53.367,7.029 cw(c53.48,7.029) 53.594,7.029 53.594,6.958 ccw(c53.721,6.958) 53.721,6.831 54.011,6.831 88.533,6.831 91.421,9.718 91.421,13.019 90.17,14.27 90.17,16.913 90.05,17.032 v1(90.05,17.09)
CSI_A_DATA1_N: J1.88 J12.12 | length 52.8
  Top Layer w0.127: v1(51.29,7.3) 51.293,7.3 51.42,7.426 51.42,7.62 51.348,7.692 J1.88@51.348,8.229 ; v1(90.92,15.2) 90.978,15.2 91.098,15.08 J12.12@92.297,15.08
  Bottom Layer w0.127: v1(51.29,7.3) 51.29,7.257 51.425,7.123 51.425,6.767 52.341,5.85 88.98,5.85 92.42,9.29 92.42,14.381 91.721,15.081 90.994,15.081 90.92,15.155 v1(90.92,15.2)
CSI_A_DATA1_P: J1.86 J12.11 | length 52.8
  Top Layer w0.127: J1.86@51.748,8.229 51.748,7.688 51.68,7.62 51.68,7.426 51.8,7.307 v1(51.8,7.3) ; v1(90.92,14.7) 90.978,14.7 91.097,14.82 J12.11@92.297,14.82
  Bottom Layer w0.127: v1(51.8,7.3) 51.8,7.237 51.685,7.123 51.685,6.875 52.449,6.111 88.872,6.111 92.159,9.398 92.159,13.374 92.159,13.574 ccw(c92.032,13.574) 92.032,13.701 91.803,13.701 cw(c91.803,13.814) 91.803,13.928 92.046,13.928 ccw(c92.046,14.041) 92.046,14.155 91.679,14.155 cw(c91.679,14.268) 91.679,14.382 91.745,14.382 ccw(c91.745,14.509) 91.834,14.598 91.704,14.729 91.613,14.82 90.994,14.82 90.92,14.746 v1(90.92,14.7)
CSI_A_DATA2_N: J1.94 J12.6 | length 53.9
  Top Layer w0.127: v1(50.1,7.29) 50.1,7.307 50.22,7.427 50.22,7.62 50.15,7.69 J1.94@50.15,7.94 ; J12.6@92.435,12.2 92.435,12.092 92.442,12.086 92.95,12.086 92.998,12.133 93.088,12.133 v1@93.14,12.08
  Int2 (Sign) w0.1: v1(50.1,7.29) 50.1,7.209 50.19,7.119 50.19,6.79 50.507,6.473 55.844,6.473 ccw(c55.844,6.89) 56.261,6.89 56.261,7.189 cw(c56.361,7.189) 56.461,7.189 56.461,6.783 ccw(c56.878,6.783) 57.295,6.783 57.295,7.316 cw(c57.395,7.316) 57.495,7.316 57.495,6.783 ccw(c57.911,6.783) 58.328,6.783 58.328,7.316 cw(c58.428,7.316) 58.528,7.316 58.528,6.89 ccw(c58.945,6.89) 58.945,6.473 86.903,6.473 91.143,10.713 93.431,10.713 93.83,11.112 93.83,11.818 93.551,12.097 93.293,12.097 93.201,12.188 v1(93.12,12.188)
